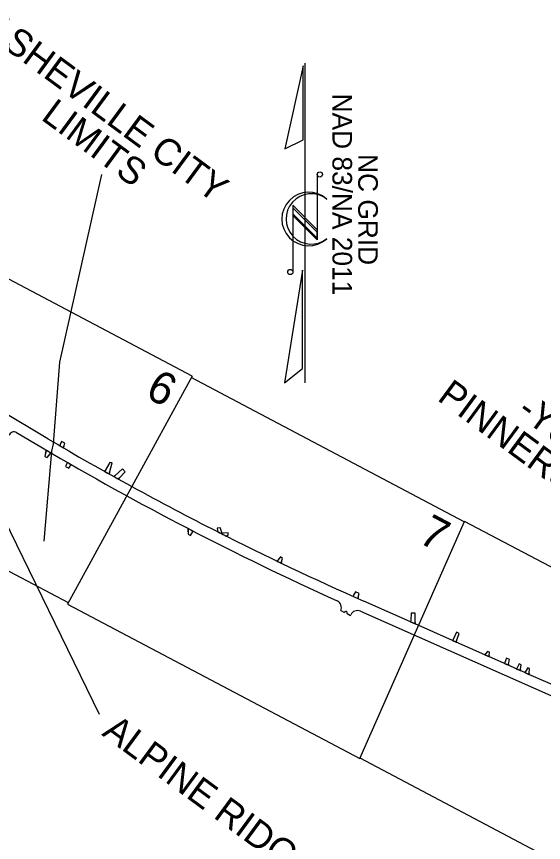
# Model space of a CAD drawing. Extents: x 945666 to 965748, y 644452 to 663300.
# Drawn here: x 954496 to 956642, y 652491 to 655852 of the extents above; entities that cross this region are included whole.
import ezdxf

# ---------------------------------------------------------------- set-up
doc = ezdxf.new("R2010")
doc.units = 0
for name, color, linetype in [('Exist Boundary Political City Limit New', 7, 'Continuous'), ('Old_Level_23', 7, 'Continuous'), ('Prop EOT', 7, 'Continuous'), ('Prop Shade Light', 7, 'Continuous'), ('Sheet North Arrow CELL', 7, 'Continuous'), ('Sheet Plan Layout CELL', 7, 'Continuous')]:
    doc.layers.add(name, color=color, linetype=linetype)

msp = doc.modelspace()

# ---------------------------------------------------------------- linework, layer by layer
at = {"layer": 'Exist Boundary Political City Limit New'}
for p, q in [((954671.1, 654445.5), (954645.3, 654112.9)), ((954645.3, 654112.9), (954637.5, 654082.7)), ((954637.5, 654082.7), (954606.4, 653716.6))]:
    msp.add_line(p, q, dxfattribs=at)
at = {"layer": 'Old_Level_23'}
for p, q in [((954842, 655209.1), (954671.1, 654445.5)), ((954241.6, 654222.8), (954832.4, 653013.2))]:
    msp.add_line(p, q, dxfattribs=at)
at = {"layer": 'Prop EOT'}
for p, q in [((954674, 654109.5), (954672.2, 654104.8)), ((954614.2, 654074.4), (954618.1, 654086.6)), ((954628, 654066.3), (954636.1, 654076.1)), ((954687.8, 654101.5), (954686.1, 654096.7)), ((954697.8, 654025.8), (954703.3, 654037.1)), ((954711.6, 654017.9), (954718.2, 654028.5)), ((954857.1, 654004.9), (954854.7, 654000.5)), ((954874.6, 653995.1), (954873.3, 653990.1)), ((954896.3, 653983), (954892.2, 653979.6)), ((954913.9, 653973.3), (954910.6, 653969.4)), ((955194.7, 653754.3), (955194.7, 653768.1)), ((955208.9, 653747), (955215.6, 653757.6)), ((955313.8, 653761.2), (955313.8, 653755.6)), ((955331.7, 653752.2), (955331.7, 653746.8)), ((955337, 653749.5), (955332.2, 653746.3)), ((955354.9, 653740.5), (955349.7, 653737.5)), ((955560.5, 653639.5), (955557.8, 653635.2)), ((955574.9, 653632.6), (955573.6, 653627.6)), ((955868.7, 653496.5), (955866.6, 653492)), ((955887, 653488.4), (955885.8, 653483.5)), ((956101.2, 653393.5), (956100.2, 653388.5)), ((956119.5, 653385.4), (956119.5, 653379.9)), ((956273.6, 653317.2), (956271.5, 653312.7)), ((956288.2, 653310.7), (956286.5, 653306)), ((956406, 653258.6), (956403, 653254.4)), ((956420.6, 653252.1), (956419.5, 653247.1)), ((956485.2, 653223.5), (956483.8, 653218.7)), ((956499.9, 653217), (956498.8, 653212)), ((956534.1, 653201.9), (956531.3, 653197.6)), ((956548.7, 653195.4), (956547.5, 653190.5)), ((956568.5, 653186.6), (956566, 653182.3)), ((956583.2, 653180.1), (956582.5, 653175))]:
    msp.add_line(p, q, dxfattribs=at)
at = {"layer": 'Prop Shade Light'}
for p, q in [((954495.6, 654158.7), (954601.7, 654096.2)), ((954674, 654109.6), (954672.2, 654104.8)), ((954679.2, 654122.5), (954674, 654109.6)), ((954692.8, 654115.5), (954679.2, 654122.5)), ((954687.8, 654101.5), (954692.8, 654115.5)), ((954614.2, 654074.4), (954611.4, 654061.9)), ((954618.1, 654086.6), (954614.2, 654074.4)), ((954628, 654066.3), (954636.1, 654076.1)), ((954686.1, 654096.7), (954687.8, 654101.5)), ((954611.4, 654061.9), (954620.4, 654057.5)), ((954620.4, 654057.5), (954628, 654066.3)), ((954697.8, 654025.9), (954695.7, 654021.3)), ((954703.3, 654037.1), (954697.8, 654025.9)), ((954711.6, 654017.9), (954718.2, 654028.5)), ((954875.9, 654037.6), (954857.1, 654004.9)), ((954874.6, 653995.2), (954885.5, 654035.7)), ((954885.5, 654035.7), (954875.9, 654037.6)), ((954927.6, 654011.8), (954896.3, 653983.1)), ((954937.6, 653998.4), (954927.6, 654011.8)), ((954857.1, 654004.9), (954854.7, 654000.6)), ((954873.3, 653990.2), (954874.6, 653995.2)), ((954896.3, 653983.1), (954892.2, 653979.6)), ((954910.6, 653969.4), (954913.9, 653973.3)), ((954913.9, 653973.3), (954937.6, 653998.4)), ((955326.7, 653771.4), (955313.5, 653770)), ((955194.7, 653768.2), (955194.7, 653754.3)), ((955194.7, 653754.3), (955195.3, 653745.4)), ((955195.3, 653745.4), (955204.5, 653740.6)), ((955204.5, 653740.6), (955208.9, 653747)), ((955208.9, 653747), (955215.6, 653757.6)), ((955313.5, 653770), (955313.8, 653761.3)), ((955313.8, 653761.3), (955313.8, 653755.7)), ((955313.8, 653755.6), (955313.8, 653755.7)), ((955331.7, 653746.8), (955331.7, 653752.2)), ((955337, 653749.5), (955331.7, 653746.8)), ((955358.1, 653750.5), (955337, 653749.5)), ((955349.7, 653737.5), (955354.9, 653740.5)), ((955354.9, 653740.5), (955357.8, 653741.9)), ((955357.8, 653741.9), (955358.1, 653750.5)), ((955560.4, 653639.5), (955557.8, 653635.2)), ((955573.6, 653627.7), (955574.9, 653632.6)), ((955876.3, 653511.4), (955868.7, 653496.6)), ((955890.7, 653504.5), (955876.3, 653511.4)), ((955887, 653488.4), (955890.7, 653504.5)), ((955868.7, 653496.6), (955866.6, 653492)), ((955885.8, 653483.5), (955887, 653488.4)), ((956100.2, 653388.5), (955910.7, 653472.4)), ((955816, 653434.2), (955831.1, 653426.9)), ((955841.7, 653422), (955855.9, 653415.1)), ((955855.9, 653415.1), (955857.1, 653417.5)), ((955896.2, 653431.8), (956727.8, 653063.6)), ((956101.2, 653393.6), (956100.2, 653388.5)), ((956119.5, 653380), (956100.2, 653388.5)), ((956100.2, 653388.5), (956119.5, 653380)), ((956119.5, 653380), (956119.5, 653385.5)), ((956271.4, 653312.7), (956119.5, 653380)), ((956119.5, 653380), (956119.5, 653380)), ((956273.6, 653317.2), (956271.4, 653312.7)), ((956271.4, 653312.7), (956286.5, 653306)), ((956286.5, 653306), (956288.2, 653310.7)), ((956414.3, 653268.6), (956406, 653258.6)), ((956422.7, 653264.9), (956414.3, 653268.6)), ((956406, 653258.6), (956403, 653254.5)), ((956419.5, 653247.2), (956414.9, 653249.2)), ((956419.5, 653247.2), (956420.6, 653252.1)), ((956420.6, 653252.1), (956422.7, 653264.9)), ((956491, 653241.2), (956485.2, 653223.5)), ((956503, 653235.9), (956491, 653241.2)), ((956499.9, 653217), (956503, 653235.9)), ((956485.2, 653223.5), (956483.8, 653218.7)), ((956483.8, 653218.7), (956498.8, 653212.1)), ((956498.8, 653212.1), (956499.9, 653217)), ((956534.1, 653201.9), (956531.3, 653197.7)), ((956542.8, 653217.1), (956534.1, 653201.9)), ((956550.9, 653213.5), (956542.8, 653217.1)), ((956548.7, 653195.4), (956550.9, 653213.5)), ((956578.4, 653201.3), (956568.5, 653186.6)), ((956585, 653198.4), (956578.4, 653201.3)), ((956547.5, 653190.5), (956531.3, 653197.7)), ((956531.3, 653197.7), (956547.5, 653190.5)), ((956547.5, 653190.5), (956548.7, 653195.4)), ((956568.5, 653186.6), (956566, 653182.3)), ((956566, 653182.3), (956582.5, 653175)), ((956582.5, 653175), (956583.1, 653180.2)), ((956745.2, 653103), (956582.5, 653175)), ((956583.1, 653180.2), (956585, 653198.4))]:
    msp.add_line(p, q, dxfattribs=at)
for points in [[(954623.6, 654133.3), (954421.9, 654252), (954406.4, 654261.1), (954313.3, 654315.9), (954298, 654324.8), (954227.6, 654366.3)], [(954695.7, 654021.3), (954708.9, 654013.7), (954711.6, 654017.9)], [(955331.7, 653752.2), (955328.5, 653763.7), (955326.7, 653771.4)], [(955194.8, 653768.4), (955194.7, 653768.2)], [(955313.8, 653755.6), (955313.8, 653755.6)], [(955331.6, 653746.7), (955331.7, 653746.8)], [(955331.7, 653746.8), (955331.6, 653746.7)], [(955574.9, 653632.6), (955579.1, 653646.4), (955570.6, 653652.8), (955560.4, 653639.5)], [(956119.5, 653385.5), (956118.7, 653423.9), (956103.5, 653423.4), (956101.2, 653393.6)], [(956119.5, 653380), (956119.5, 653380)], [(956288.2, 653310.7), (956298.8, 653341.6), (956288.1, 653346.2), (956273.6, 653317.2)], [(956414.9, 653249.2), (956403, 653254.5), (956286.5, 653306), (956271.4, 653312.7)], [(956403, 653254.5), (956414.9, 653249.2), (956419.5, 653247.2)], [(956531.3, 653197.7), (956498.8, 653212.1), (956483.8, 653218.7), (956419.5, 653247.2)], [(956582.5, 653175), (956566, 653182.3), (956547.5, 653190.5)]]:
    msp.add_lwpolyline(points, dxfattribs=at)
for centre, radius, start, end in [((954485.5, 654141.4), 20, 59.525, 166.1716), ((961002.9, 664974.1), 12578.5, 239.525, 243.10954), ((961002.9, 664974.1), 12621.5, 239.525, 245.66151), ((961002.9, 664974.1), 12621.5, 239.61087, 239.70575), ((961002.9, 664974.1), 12578.5, 239.7816, 239.85484), ((961002.9, 664974.1), 12621.5, 240.05824, 240.13644), ((961002.9, 664974.1), 12578.5, 240.739, 240.836), ((961002.9, 664974.1), 12578.5, 240.93488, 241.03051), ((961002.9, 664974.1), 12621.5, 242.60161, 242.70786), ((961002.9, 664974.1), 12578.5, 243.10954, 243.20035), ((961002.9, 664974.1), 12578.5, 243.10967, 246.11932), ((961002.9, 664974.1), 12578.5, 243.20035, 243.29251), ((961002.9, 664974.1), 12578.5, 244.34889, 244.42866), ((955788.9, 653447), 30, 334.7759, 65.6615), ((961002.9, 664974.1), 12578.5, 245.89948, 245.9951), ((955836.8, 653425.4), 5.93, 325.4339, 164.6212), ((955884.1, 653404.4), 30, 66.1338, 154.0105)]:
    msp.add_arc(centre, radius, start, end, dxfattribs=at)
at = {"layer": 'Sheet North Arrow CELL'}
for p, q in [((955671.7, 654361.6), (955671.7, 655661.6)), ((955720.7, 655209.2), (955720.7, 654942.4)), ((955720.7, 654984), (955621.3, 655083.4)), ((955621.3, 655083.4), (955621.3, 654812.2)), ((955757.5, 655109.8), (955758.9, 655108.8)), ((955720.7, 654974.2), (955621.3, 655073.6)), ((955621.3, 655073.6), (955621.3, 655049.2)), ((955720.7, 654949.8), (955621.3, 655049.2)), ((955621.3, 655049.2), (955720.7, 654949.8)), ((955720.7, 654942.4), (955621.3, 655041.8)), ((955720.7, 654949.8), (955720.7, 654974.2))]:
    msp.add_line(p, q, dxfattribs=at)
for points in [[(955662.7, 655650.2), (955588.5, 655312.6), (955662.7, 655350.2)], [(955661.1, 654819.6), (955587.5, 654361.6), (955661.1, 654419.6)]]:
    msp.add_lwpolyline(points, close=True, dxfattribs=at)
for centre in [(955731.3, 655209), (955610.7, 654811.8)]:
    msp.add_circle(centre, 10.6, dxfattribs=at)
for centre, radius, start, end in [((955685.5, 655027.8), 109.2, 47.84, 312.3941), ((955696.1, 655027.9), 102.4, 53.095, 308.6287)]:
    msp.add_arc(centre, radius, start, end, dxfattribs=at)
at = {"layer": 'Sheet Plan Layout CELL'}
for p, q in [((955210.6, 654388.3), (954074.6, 654988.1)), ((955210.6, 654388.3), (954703.3, 653461.1)), ((956319.5, 653795), (955207.3, 654382.3)), ((953541.5, 654082.2), (954706.6, 653467.1)), ((955893.4, 652832.6), (956320.5, 653797.4)), ((957441.2, 653205.6), (956320.5, 653797.4)), ((954703.3, 653461.1), (955893.4, 652832.6)), ((955894.4, 652835), (956681.5, 652419.4))]:
    msp.add_line(p, q, dxfattribs=at)

# ---------------------------------------------------------------- texts
at = {"layer": 'Old_Level_23'}
for s, p in [('ASHEVILLE CITY', (954356.3, 655787.7)), ('LIMITS', (954591.3, 655435.1)), ('PINNERS COVE RD.', (956205.2, 654293)), ('-Y6- SR 3121', (956529.1, 654233.4)), ('ALPINE RIDGE DR.', (954839.5, 652929.6))]:
    msp.add_text(s, height=110, rotation=323.5908, dxfattribs=at).set_placement(p)
at = {"layer": 'Sheet North Arrow CELL'}
for s, p in [('     NAD 83/NA 2011', (955782.4, 655686.5)), ('NC GRID', (955887.2, 655291.7))]:
    msp.add_text(s, height=80, rotation=270, dxfattribs=at).set_placement(p)
at = {"layer": 'Sheet Plan Layout CELL'}
for s, p in [('6', (955015, 654305.6)), ('7', (956126.4, 653715.1))]:
    msp.add_text(s, height=131.3, rotation=332.1644, dxfattribs=at).set_placement(p)

doc.saveas('drawing.dxf')
